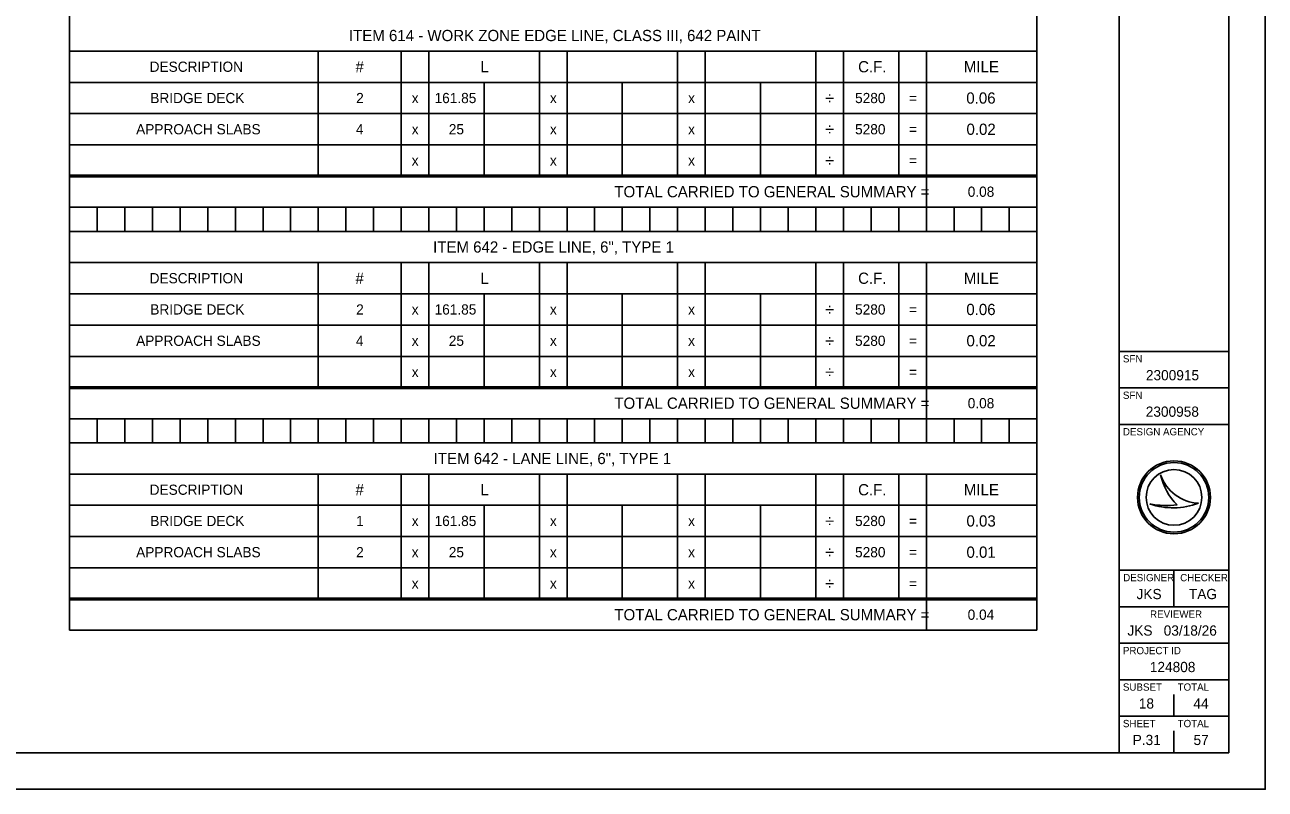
# Model space of a CAD drawing. Extents: x 0 to 34, y 0 to 22.
# Drawn here: x 17 to 34, y 0 to 10.48 of the extents above; entities that cross this region are included whole.
import ezdxf

# ---------------------------------------------------------------- set-up
doc = ezdxf.new("R2010")
doc.units = 0
for name, color, linetype in [('SH_Border', 7, 'Continuous'), ('SH_Cut_Line', 7, 'Continuous'), ('SH_Data', 7, 'Continuous'), ('SH_Text', 7, 'Continuous')]:
    doc.layers.add(name, color=color, linetype=linetype)

msp = doc.modelspace()

# ---------------------------------------------------------------- linework, layer by layer
at = {"layer": 'SH_Border'}
for p, q in [((32, 0.5), (32, 21.5)), ((32, 6), (33.5, 6)), ((32, 5.5), (33.5, 5.5)), ((32, 5), (33.5, 5)), ((32, 3), (33.5, 3)), ((32.75, 3), (32.75, 2.5)), ((32, 2.5), (33.5, 2.5)), ((32, 2), (33.5, 2)), ((32, 1.5), (33.5, 1.5)), ((32, 1), (33.5, 1))]:
    msp.add_line(p, q, dxfattribs=at)
msp.add_lwpolyline([(1.5, 21.5), (33.5, 21.5), (33.5, 0.5), (1.5, 0.5)], close=True, dxfattribs=at)
at = {"layer": 'SH_Cut_Line'}
msp.add_lwpolyline([(0, 0), (34, 0), (34, 22), (0, 22)], close=True, dxfattribs=at)
at = {"layer": 'SH_Data'}
for p, q in [((32.75, 5.675), (32.75, 5.675)), ((32.75, 5.175), (32.75, 5.175)), ((32.567, 4.31), (32.567, 4.31)), ((32.75, 4), (32.75, 4)), ((33.087, 3.919), (33.087, 3.919)), ((32.417, 3.91), (32.417, 3.91)), ((32.75, 1), (32.75, 1.3)), ((32.75, 0.5), (32.75, 0.8)), ((32.375, 0.675), (32.375, 0.675))]:
    msp.add_line(p, q, dxfattribs=at)
for radius in [0.5, 0.477, 0.477, 0.382]:
    msp.add_circle((32.75, 4), radius, dxfattribs=at)
for centre, radius, start, end in [((33.116, 4.498), 0.58, 198.9257, 198.9319), ((33.347, 4.47), 0.796, 191.6379, 191.6421), ((33.116, 4.498), 0.58, 198.9319, 267.1657), ((33.347, 4.47), 0.796, 191.6421, 226.0947), ((32.739, 4.87), 1.013, 251.4576, 290.0832), ((32.648, 5.154), 1.266, 259.4964, 259.4995), ((32.739, 4.87), 1.013, 251.4527, 251.4576), ((32.648, 5.154), 1.266, 259.4995, 276.6672)]:
    msp.add_arc(centre, radius, start, end, dxfattribs=at)
at = {"layer": 'SH_Text'}
for p, q in [((17.613, 11.314), (17.613, 8.393)), ((30.872, 11.314), (30.872, 8.393)), ((17.613, 10.117), (30.872, 10.117)), ((21.022, 10.117), (21.022, 8.415)), ((22.159, 10.117), (22.159, 8.415)), ((22.538, 10.117), (22.538, 8.415)), ((24.053, 10.117), (24.053, 8.415)), ((24.432, 10.117), (24.432, 8.415)), ((25.947, 10.117), (25.947, 8.415)), ((26.326, 10.117), (26.326, 8.415)), ((27.841, 10.117), (27.841, 8.415)), ((28.22, 10.117), (28.22, 8.415)), ((28.978, 10.117), (28.978, 8.415)), ((29.356, 10.117), (29.356, 8.415)), ((17.613, 9.689), (30.872, 9.689)), ((23.295, 9.689), (23.295, 8.415)), ((25.189, 9.689), (25.189, 8.415)), ((27.083, 9.689), (27.083, 8.415)), ((17.613, 9.26), (30.872, 9.26)), ((17.613, 8.832), (30.872, 8.832)), ((17.613, 8.415), (30.872, 8.415)), ((17.613, 8.415), (17.613, 5.494)), ((17.613, 8.393), (30.872, 8.393)), ((29.356, 8.393), (29.356, 7.976)), ((30.872, 8.415), (30.872, 5.494)), ((17.613, 7.976), (30.872, 7.976)), ((17.613, 7.646), (30.872, 7.646)), ((17.613, 7.218), (30.872, 7.218)), ((21.022, 7.218), (21.022, 5.516)), ((22.159, 7.218), (22.159, 5.516)), ((22.538, 7.218), (22.538, 5.516)), ((24.053, 7.218), (24.053, 5.516)), ((24.432, 7.218), (24.432, 5.516)), ((25.947, 7.218), (25.947, 5.516)), ((26.326, 7.218), (26.326, 5.516)), ((27.841, 7.218), (27.841, 5.516)), ((28.22, 7.218), (28.22, 5.516)), ((28.978, 7.218), (28.978, 5.516)), ((29.356, 7.218), (29.356, 5.516)), ((17.613, 6.79), (30.872, 6.79)), ((23.295, 6.79), (23.295, 5.516)), ((25.189, 6.79), (25.189, 5.516)), ((27.083, 6.79), (27.083, 5.516)), ((17.613, 6.362), (30.872, 6.362)), ((17.613, 5.933), (30.872, 5.933)), ((17.613, 5.516), (30.872, 5.516)), ((17.613, 5.516), (17.613, 2.595)), ((17.613, 5.494), (30.872, 5.494)), ((29.356, 5.494), (29.356, 5.077)), ((30.872, 5.516), (30.872, 2.595)), ((17.613, 5.077), (30.872, 5.077)), ((17.613, 4.747), (30.872, 4.747)), ((17.613, 4.319), (30.872, 4.319)), ((21.022, 4.319), (21.022, 2.617)), ((22.159, 4.319), (22.159, 2.617)), ((22.538, 4.319), (22.538, 2.617)), ((24.053, 4.319), (24.053, 2.617)), ((24.432, 4.319), (24.432, 2.617)), ((25.947, 4.319), (25.947, 2.617)), ((26.326, 4.319), (26.326, 2.617)), ((27.841, 4.319), (27.841, 2.617)), ((28.22, 4.319), (28.22, 2.617)), ((28.978, 4.319), (28.978, 2.617)), ((29.356, 4.319), (29.356, 2.617)), ((17.613, 3.891), (30.872, 3.891)), ((23.295, 3.891), (23.295, 2.617)), ((25.189, 3.891), (25.189, 2.617)), ((27.083, 3.891), (27.083, 2.617)), ((17.613, 3.463), (30.872, 3.463)), ((17.613, 3.034), (30.872, 3.034)), ((17.613, 2.617), (30.872, 2.617)), ((17.613, 2.617), (17.613, 2.178)), ((17.613, 2.595), (30.872, 2.595)), ((29.356, 2.595), (29.356, 2.178)), ((30.872, 2.617), (30.872, 2.178)), ((17.613, 2.178), (30.872, 2.178))]:
    msp.add_line(p, q, dxfattribs=at)
for points in [[(17.613, 7.976), (17.992, 7.976), (17.992, 7.646), (17.613, 7.646)], [(17.992, 7.976), (18.37, 7.976), (18.37, 7.646), (17.992, 7.646)], [(18.37, 7.976), (18.749, 7.976), (18.749, 7.646), (18.37, 7.646)], [(18.749, 7.976), (19.128, 7.976), (19.128, 7.646), (18.749, 7.646)], [(19.128, 7.976), (19.507, 7.976), (19.507, 7.646), (19.128, 7.646)], [(19.507, 7.976), (19.886, 7.976), (19.886, 7.646), (19.507, 7.646)], [(19.886, 7.976), (20.265, 7.976), (20.265, 7.646), (19.886, 7.646)], [(20.265, 7.976), (20.643, 7.976), (20.643, 7.646), (20.265, 7.646)], [(20.643, 7.976), (21.022, 7.976), (21.022, 7.646), (20.643, 7.646)], [(21.022, 7.976), (21.401, 7.976), (21.401, 7.646), (21.022, 7.646)], [(21.401, 7.976), (21.78, 7.976), (21.78, 7.646), (21.401, 7.646)], [(21.78, 7.976), (22.159, 7.976), (22.159, 7.646), (21.78, 7.646)], [(22.159, 7.976), (22.538, 7.976), (22.538, 7.646), (22.159, 7.646)], [(22.538, 7.976), (22.916, 7.976), (22.916, 7.646), (22.538, 7.646)], [(22.916, 7.976), (23.295, 7.976), (23.295, 7.646), (22.916, 7.646)], [(23.295, 7.976), (23.674, 7.976), (23.674, 7.646), (23.295, 7.646)], [(23.674, 7.976), (24.053, 7.976), (24.053, 7.646), (23.674, 7.646)], [(24.053, 7.976), (24.432, 7.976), (24.432, 7.646), (24.053, 7.646)], [(24.432, 7.976), (24.81, 7.976), (24.81, 7.646), (24.432, 7.646)], [(24.81, 7.976), (25.189, 7.976), (25.189, 7.646), (24.81, 7.646)], [(25.189, 7.976), (25.568, 7.976), (25.568, 7.646), (25.189, 7.646)], [(25.568, 7.976), (25.947, 7.976), (25.947, 7.646), (25.568, 7.646)], [(25.947, 7.976), (26.326, 7.976), (26.326, 7.646), (25.947, 7.646)], [(26.326, 7.976), (26.705, 7.976), (26.705, 7.646), (26.326, 7.646)], [(26.705, 7.976), (27.083, 7.976), (27.083, 7.646), (26.705, 7.646)], [(27.083, 7.976), (27.462, 7.976), (27.462, 7.646), (27.083, 7.646)], [(27.462, 7.976), (27.841, 7.976), (27.841, 7.646), (27.462, 7.646)], [(27.841, 7.976), (28.22, 7.976), (28.22, 7.646), (27.841, 7.646)], [(28.22, 7.976), (28.599, 7.976), (28.599, 7.646), (28.22, 7.646)], [(28.599, 7.976), (28.978, 7.976), (28.978, 7.646), (28.599, 7.646)], [(28.978, 7.976), (29.356, 7.976), (29.356, 7.646), (28.978, 7.646)], [(29.356, 7.976), (29.735, 7.976), (29.735, 7.646), (29.356, 7.646)], [(29.735, 7.976), (30.114, 7.976), (30.114, 7.646), (29.735, 7.646)], [(30.114, 7.976), (30.493, 7.976), (30.493, 7.646), (30.114, 7.646)], [(30.493, 7.976), (30.872, 7.976), (30.872, 7.646), (30.493, 7.646)], [(17.613, 5.077), (17.992, 5.077), (17.992, 4.747), (17.613, 4.747)], [(17.992, 5.077), (18.37, 5.077), (18.37, 4.747), (17.992, 4.747)], [(18.37, 5.077), (18.749, 5.077), (18.749, 4.747), (18.37, 4.747)], [(18.749, 5.077), (19.128, 5.077), (19.128, 4.747), (18.749, 4.747)], [(19.128, 5.077), (19.507, 5.077), (19.507, 4.747), (19.128, 4.747)], [(19.507, 5.077), (19.886, 5.077), (19.886, 4.747), (19.507, 4.747)], [(19.886, 5.077), (20.265, 5.077), (20.265, 4.747), (19.886, 4.747)], [(20.265, 5.077), (20.643, 5.077), (20.643, 4.747), (20.265, 4.747)], [(20.643, 5.077), (21.022, 5.077), (21.022, 4.747), (20.643, 4.747)], [(21.022, 5.077), (21.401, 5.077), (21.401, 4.747), (21.022, 4.747)], [(21.401, 5.077), (21.78, 5.077), (21.78, 4.747), (21.401, 4.747)], [(21.78, 5.077), (22.159, 5.077), (22.159, 4.747), (21.78, 4.747)], [(22.159, 5.077), (22.538, 5.077), (22.538, 4.747), (22.159, 4.747)], [(22.538, 5.077), (22.916, 5.077), (22.916, 4.747), (22.538, 4.747)], [(22.916, 5.077), (23.295, 5.077), (23.295, 4.747), (22.916, 4.747)], [(23.295, 5.077), (23.674, 5.077), (23.674, 4.747), (23.295, 4.747)], [(23.674, 5.077), (24.053, 5.077), (24.053, 4.747), (23.674, 4.747)], [(24.053, 5.077), (24.432, 5.077), (24.432, 4.747), (24.053, 4.747)], [(24.432, 5.077), (24.81, 5.077), (24.81, 4.747), (24.432, 4.747)], [(24.81, 5.077), (25.189, 5.077), (25.189, 4.747), (24.81, 4.747)], [(25.189, 5.077), (25.568, 5.077), (25.568, 4.747), (25.189, 4.747)], [(25.568, 5.077), (25.947, 5.077), (25.947, 4.747), (25.568, 4.747)], [(25.947, 5.077), (26.326, 5.077), (26.326, 4.747), (25.947, 4.747)], [(26.326, 5.077), (26.705, 5.077), (26.705, 4.747), (26.326, 4.747)], [(26.705, 5.077), (27.083, 5.077), (27.083, 4.747), (26.705, 4.747)], [(27.083, 5.077), (27.462, 5.077), (27.462, 4.747), (27.083, 4.747)], [(27.462, 5.077), (27.841, 5.077), (27.841, 4.747), (27.462, 4.747)], [(27.841, 5.077), (28.22, 5.077), (28.22, 4.747), (27.841, 4.747)], [(28.22, 5.077), (28.599, 5.077), (28.599, 4.747), (28.22, 4.747)], [(28.599, 5.077), (28.978, 5.077), (28.978, 4.747), (28.599, 4.747)], [(28.978, 5.077), (29.356, 5.077), (29.356, 4.747), (28.978, 4.747)], [(29.356, 5.077), (29.735, 5.077), (29.735, 4.747), (29.356, 4.747)], [(29.735, 5.077), (30.114, 5.077), (30.114, 4.747), (29.735, 4.747)], [(30.114, 5.077), (30.493, 5.077), (30.493, 4.747), (30.114, 4.747)], [(30.493, 5.077), (30.872, 5.077), (30.872, 4.747), (30.493, 4.747)]]:
    msp.add_lwpolyline(points, close=True, dxfattribs=at)

# ---------------------------------------------------------------- texts
at = {"layer": 'SH_Data'}
for s, height, p in [('SFN', 0.1, (32.05, 5.85)), ('2300915', 0.14, (32.365, 5.605)), ('SFN', 0.1, (32.05, 5.35)), ('2300958', 0.14, (32.363, 5.105)), ('DESIGN AGENCY', 0.1, (32.05, 4.85)), ('DESIGNER', 0.1, (32.054, 2.85)), ('CHECKER', 0.1, (32.835, 2.85)), ('JKS', 0.14, (32.237, 2.605)), ('TAG', 0.14, (32.955, 2.605)), ('REVIEWER', 0.1, (32.422, 2.35)), ('JKS', 0.14, (32.112, 2.105)), ('03/18/26', 0.14, (32.609, 2.105)), ('PROJECT ID', 0.1, (32.05, 1.85)), ('124808', 0.14, (32.419, 1.605)), ('SUBSET', 0.1, (32.05, 1.35)), ('TOTAL', 0.1, (32.8, 1.35)), ('18', 0.14, (32.268, 1.105)), ('44', 0.14, (33.016, 1.105)), ('SHEET', 0.1, (32.05, 0.85)), ('TOTAL', 0.1, (32.8, 0.85)), ('P.31', 0.14, (32.184, 0.605)), ('57', 0.14, (33.018, 0.605))]:
    msp.add_text(s, height=height, dxfattribs=at).set_placement(p)
at = {"layer": 'SH_Text'}
for s, height, p in [('ITEM 614 - WORK ZONE EDGE LINE, CLASS III, 642 PAINT', 0.154, (21.442, 10.254)), ('DESCRIPTION', 0.14, (18.711, 9.833)), ('#', 0.154, (21.532, 9.826)), ('L', 0.154, (23.245, 9.826)), ('C.F.', 0.154, (28.421, 9.826)), ('MILE', 0.154, (29.87, 9.826)), ('BRIDGE DECK', 0.14, (18.72, 9.404)), ('2', 0.14, (21.541, 9.404)), ('161.85', 0.14, (22.616, 9.404)), ('÷', 0.168, (27.968, 9.39)), ('5280', 0.14, (28.379, 9.404)), ('0.06', 0.154, (29.904, 9.397)), ('x', 0.14, (22.303, 9.404)), ('x', 0.14, (24.197, 9.404)), ('x', 0.14, (26.091, 9.404)), ('=', 0.14, (29.117, 9.404)), ('APPROACH SLABS', 0.14, (18.526, 8.976)), ('4', 0.14, (21.538, 8.976)), ('x', 0.14, (22.303, 8.976)), ('25', 0.14, (22.811, 8.976)), ('x', 0.14, (24.197, 8.976)), ('x', 0.14, (26.091, 8.976)), ('÷', 0.168, (27.968, 8.962)), ('5280', 0.14, (28.379, 8.976)), ('=', 0.14, (29.117, 8.976)), ('0.02', 0.154, (29.906, 8.969)), ('÷', 0.168, (27.968, 8.534)), ('x', 0.14, (22.303, 8.548)), ('x', 0.14, (24.197, 8.548)), ('x', 0.14, (26.091, 8.548)), ('=', 0.14, (29.117, 8.548)), ('TOTAL CARRIED TO GENERAL SUMMARY =', 0.154, (25.08, 8.113)), ('0.08', 0.14, (29.923, 8.12)), ('ITEM 642 - EDGE LINE, 6", TYPE 1', 0.154, (22.596, 7.355)), ('DESCRIPTION', 0.14, (18.711, 6.934)), ('#', 0.154, (21.532, 6.927)), ('L', 0.154, (23.245, 6.927)), ('C.F.', 0.154, (28.421, 6.927)), ('MILE', 0.154, (29.87, 6.927)), ('BRIDGE DECK', 0.14, (18.72, 6.506)), ('2', 0.14, (21.541, 6.506)), ('161.85', 0.14, (22.616, 6.506)), ('5280', 0.14, (28.379, 6.506)), ('0.06', 0.154, (29.904, 6.499)), ('x', 0.14, (22.303, 6.506)), ('x', 0.14, (24.197, 6.506)), ('x', 0.14, (26.091, 6.506)), ('÷', 0.168, (27.968, 6.492)), ('=', 0.14, (29.117, 6.506)), ('APPROACH SLABS', 0.14, (18.526, 6.077)), ('4', 0.14, (21.538, 6.077)), ('x', 0.14, (22.303, 6.077)), ('25', 0.14, (22.811, 6.077)), ('x', 0.14, (24.197, 6.077)), ('x', 0.14, (26.091, 6.077)), ('÷', 0.168, (27.968, 6.063)), ('5280', 0.14, (28.379, 6.077)), ('=', 0.14, (29.117, 6.077)), ('0.02', 0.154, (29.906, 6.07)), ('x', 0.14, (22.303, 5.649)), ('x', 0.14, (24.197, 5.649)), ('x', 0.14, (26.091, 5.649)), ('÷', 0.168, (27.968, 5.635)), ('=', 0.14, (29.117, 5.649)), ('TOTAL CARRIED TO GENERAL SUMMARY =', 0.154, (25.08, 5.214)), ('0.08', 0.14, (29.923, 5.221)), ('ITEM 642 - LANE LINE, 6", TYPE 1', 0.154, (22.604, 4.456)), ('DESCRIPTION', 0.14, (18.711, 4.035)), ('#', 0.154, (21.532, 4.028)), ('L', 0.154, (23.245, 4.028)), ('C.F.', 0.154, (28.421, 4.028)), ('MILE', 0.154, (29.87, 4.028)), ('BRIDGE DECK', 0.14, (18.72, 3.607)), ('1', 0.14, (21.541, 3.607)), ('161.85', 0.14, (22.616, 3.607)), ('5280', 0.14, (28.379, 3.607)), ('0.03', 0.154, (29.906, 3.6)), ('x', 0.14, (22.303, 3.607)), ('x', 0.14, (24.197, 3.607)), ('x', 0.14, (26.091, 3.607)), ('÷', 0.168, (27.968, 3.593)), ('=', 0.14, (29.117, 3.607)), ('APPROACH SLABS', 0.14, (18.526, 3.179)), ('2', 0.14, (21.541, 3.179)), ('x', 0.14, (22.303, 3.179)), ('25', 0.14, (22.811, 3.179)), ('x', 0.14, (24.197, 3.179)), ('x', 0.14, (26.091, 3.179)), ('÷', 0.168, (27.968, 3.165)), ('5280', 0.14, (28.379, 3.179)), ('=', 0.14, (29.117, 3.179)), ('0.01', 0.154, (29.906, 3.172)), ('x', 0.14, (22.303, 2.75)), ('x', 0.14, (24.197, 2.75)), ('x', 0.14, (26.091, 2.75)), ('÷', 0.168, (27.968, 2.736)), ('=', 0.14, (29.117, 2.75)), ('TOTAL CARRIED TO GENERAL SUMMARY =', 0.154, (25.08, 2.315)), ('0.04', 0.14, (29.922, 2.322))]:
    msp.add_text(s, height=height, dxfattribs=at).set_placement(p)

doc.saveas('drawing.dxf')
